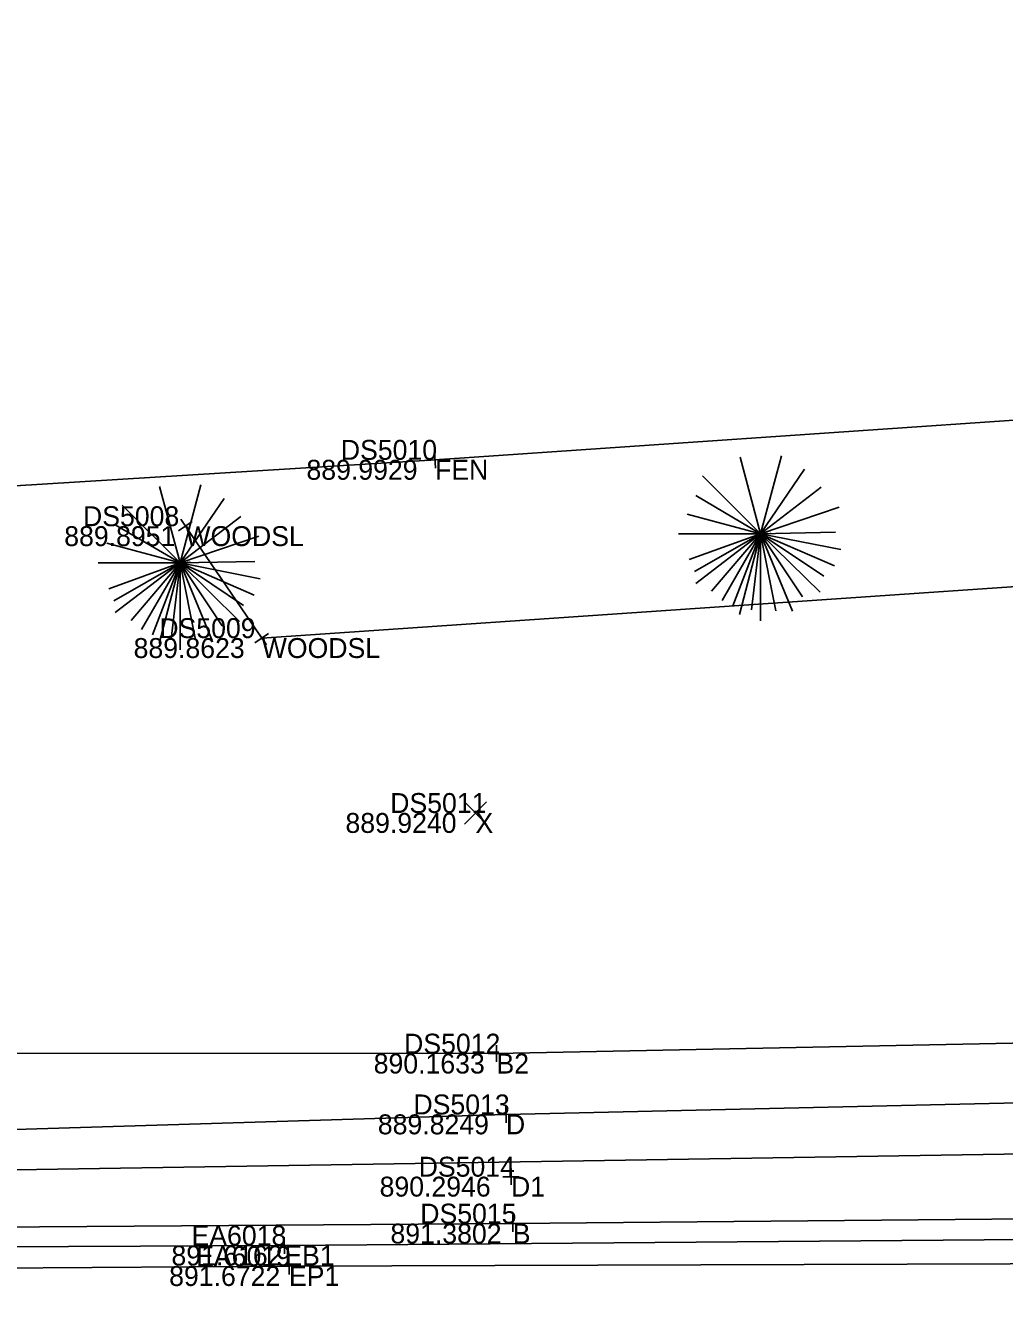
# Model space of a CAD drawing. Extents: x 179044 to 189691, y 286531 to 301257.
# Drawn here: x 179643.4 to 179702.4, y 300591.8 to 300668.9 of the extents above; entities that cross this region are included whole.
import ezdxf

# ---------------------------------------------------------------- set-up
doc = ezdxf.new("R2010")
doc.units = 0
for name, color, linetype in [('DR_X_Ditch', 7, 'Continuous'), ('PV_X_EOP', 7, 'Continuous'), ('PV_X_Shoulder_Aggregate', 7, 'Continuous'), ('RD_X_Fence', 7, 'Continuous'), ('SV_X_Break_Lines', 7, 'Continuous'), ('SV_X_Random_Point', 7, 'Continuous'), ('SV_X_Shot_Marker', 7, 'Continuous'), ('SV_X_Text_Comment', 7, 'Continuous'), ('SV_X_Text_Elevation', 7, 'Continuous'), ('SV_X_Text_Name', 7, 'Continuous'), ('VG_X_Cells', 7, 'Continuous'), ('VG_X_Text', 7, 'Continuous'), ('VG_X_Tree_Line_Rt', 7, 'Continuous')]:
    doc.layers.add(name, color=color, linetype=linetype)

msp = doc.modelspace()

# ---------------------------------------------------------------- linework, layer by layer
at = {"layer": 'DR_X_Ditch'}
msp.add_lwpolyline([(179564.56, 300599.962), (179672.339, 300603.26), (179771.172, 300605.494), (179880.337, 300606.441), (179984.937, 300607.328), (180077.947, 300608.965), (180127.19, 300616.843), (180132.045, 300619.573), (180144.286, 300623.545), (180155.547, 300629.29), (180160.465, 300633.547)], dxfattribs=at)
at = {"layer": 'PV_X_EOP'}
msp.add_lwpolyline([(179370.831, 300591.751), (179475.585, 300592.875), (179659.265, 300594.122), (179770.991, 300594.472), (179880.742, 300594.985), (179984.71, 300595.495), (180079.288, 300595.313), (180129.921, 300597.382), (180139.474, 300598.239), (180154.233, 300602.666), (180170.463, 300611.587), (180179.633, 300620.691), (180184.59, 300626.615), (180188.342, 300633.535), (180190.62, 300639.725), (180171.316, 300693.382), (180137.201, 300785.062), (180098.417, 300888.791)], dxfattribs=at)
at = {"layer": 'PV_X_Shoulder_Aggregate'}
msp.add_lwpolyline([(179563.565, 300594.924), (179658.987, 300595.359), (179770.596, 300596.259), (179881.565, 300597.129), (179984.257, 300597.357), (180079.139, 300597.322), (180129.307, 300600.299), (180139.964, 300601.425), (180153.02, 300605.118), (180169.97, 300613.883), (180177.635, 300623.691), (180181.654, 300635.111), (180182.998, 300649.235), (180167.771, 300692.69), (180134.639, 300784.201), (180095.484, 300888.508)], dxfattribs=at)
at = {"layer": 'RD_X_Fence'}
msp.add_lwpolyline([(180033.616, 300896.161), (180069.423, 300800.637), (180103.118, 300709.458), (180117.129, 300674.9), (180112.616, 300673.011), (180037.359, 300667.77), (179974.547, 300663.799), (179875.902, 300656.609), (179766.558, 300649.439), (179668.068, 300642.7), (179565.54, 300636.358)], dxfattribs=at)
at = {"layer": 'SV_X_Break_Lines'}
for points in [[(179564.638, 300606.986), (179671.768, 300606.922), (179771.087, 300608.912), (179880.599, 300615.611), (179986.884, 300616.02), (180078.033, 300615.521), (180124.742, 300624.492), (180128.289, 300624.221), (180137.303, 300629.118), (180148.459, 300633.708), (180154.503, 300636.496), (180146.307, 300651.241), (180135.969, 300673.811), (180118.542, 300716.074), (180095.911, 300772.35), (180076.611, 300824.96), (180047.5, 300900.199)], [(179564.191, 300598.682), (179770.809, 300601.942), (179880.33, 300600.557), (179984.707, 300602.17), (180076.298, 300602.513), (180129.447, 300605.473), (180133.823, 300610.665), (180143.543, 300612.063), (180154.911, 300619.358), (180168.807, 300625.749), (180172.898, 300631.66), (180174.527, 300641.071), (180168.307, 300660.619), (180157.537, 300688.57), (180123.865, 300779.294), (180087.271, 300883.216)], [(179564.385, 300595.92), (179672.75, 300596.68), (179770.459, 300597.562), (179880.51, 300598.544), (179984.703, 300599.007), (180076.342, 300598.773), (180129.476, 300602.027), (180135.94, 300603.814), (180151.807, 300606.879), (180162.976, 300612.722)]]:
    msp.add_lwpolyline(points, dxfattribs=at)
at = {"layer": 'SV_X_Random_Point'}
for p, q in [((179669.835, 300620.753), (179671.168, 300622.088)), ((179669.835, 300622.088), (179671.168, 300620.753))]:
    msp.add_line(p, q, dxfattribs=at)
at = {"layer": 'SV_X_Shot_Marker'}
for p, q in [((179668.567, 300642.735), (179667.569, 300642.666)), ((179668.102, 300642.202), (179668.034, 300643.199)), ((179668.068, 300642.7), (179668.068, 300642.7)), ((179653.439, 300638.984), (179652.613, 300638.42)), ((179652.744, 300639.115), (179653.308, 300638.289)), ((179653.026, 300638.702), (179653.026, 300638.702)), ((179658.037, 300632.241), (179657.211, 300631.677)), ((179657.343, 300632.372), (179657.906, 300631.546)), ((179657.624, 300631.959), (179657.624, 300631.959)), ((179671.768, 300607.422), (179671.768, 300606.422)), ((179671.268, 300606.922), (179672.268, 300606.921)), ((179671.768, 300606.922), (179671.768, 300606.922)), ((179671.839, 300603.245), (179672.839, 300603.276)), ((179672.324, 300603.76), (179672.354, 300602.761)), ((179672.339, 300603.26), (179672.339, 300603.26)), ((179672.144, 300599.508), (179673.144, 300599.508)), ((179672.644, 300600.008), (179672.644, 300599.008)), ((179672.644, 300599.508), (179672.644, 300599.508)), ((179672.746, 300597.18), (179672.753, 300596.18)), ((179672.25, 300596.676), (179673.25, 300596.683)), ((179672.75, 300596.68), (179672.75, 300596.68)), ((179658.985, 300595.859), (179658.989, 300594.859)), ((179658.487, 300595.357), (179659.487, 300595.361)), ((179658.987, 300595.359), (179658.987, 300595.359)), ((179658.765, 300594.119), (179659.765, 300594.126)), ((179659.262, 300594.622), (179659.268, 300593.623)), ((179659.265, 300594.122), (179659.265, 300594.122))]:
    msp.add_line(p, q, dxfattribs=at)
at = {"layer": 'VG_X_Cells'}
for p, q in [((179687.677, 300638.247), (179686.442, 300642.86)), ((179687.677, 300638.247), (179688.934, 300642.945)), ((179687.677, 300638.247), (179690.332, 300642.132)), ((179652.705, 300636.487), (179651.47, 300641.1)), ((179652.705, 300636.487), (179653.962, 300641.185)), ((179687.677, 300638.247), (179684.187, 300641.733)), ((179687.677, 300638.247), (179691.334, 300641.052)), ((179652.705, 300636.487), (179655.36, 300640.372)), ((179687.677, 300638.247), (179683.771, 300640.543)), ((179652.705, 300636.487), (179649.215, 300639.973)), ((179687.677, 300638.247), (179692.414, 300639.853)), ((179652.705, 300636.487), (179648.799, 300638.783)), ((179652.705, 300636.487), (179656.362, 300639.292)), ((179687.677, 300638.247), (179683.264, 300639.43)), ((179652.705, 300636.487), (179657.442, 300638.093)), ((179682.742, 300638.247), (179687.677, 300638.247)), ((179687.677, 300638.247), (179683.387, 300636.685)), ((179687.677, 300638.247), (179683.694, 300635.965)), ((179687.677, 300638.247), (179683.771, 300635.252)), ((179687.677, 300638.247), (179684.732, 300634.78)), ((179687.677, 300638.247), (179685.359, 300634.231)), ((179687.677, 300638.247), (179686.012, 300633.906)), ((179687.677, 300638.247), (179686.414, 300633.39)), ((179687.677, 300638.247), (179687.136, 300633.655)), ((179687.677, 300638.247), (179692.187, 300638.338)), ((179687.677, 300633.007), (179687.677, 300638.247)), ((179687.677, 300638.247), (179688.599, 300633.61)), ((179687.677, 300638.247), (179689.611, 300633.578)), ((179687.677, 300638.247), (179690.214, 300634.453)), ((179687.677, 300638.247), (179691.266, 300634.725)), ((179687.677, 300638.247), (179691.499, 300635.692)), ((179687.677, 300638.247), (179692.142, 300636.305)), ((179687.677, 300638.247), (179692.506, 300637.288)), ((179652.705, 300636.487), (179648.292, 300637.67)), ((179647.77, 300636.487), (179652.705, 300636.487)), ((179652.705, 300636.487), (179648.415, 300634.925)), ((179652.705, 300636.487), (179648.722, 300634.205)), ((179652.705, 300636.487), (179648.799, 300633.492)), ((179652.705, 300636.487), (179649.76, 300633.02)), ((179652.705, 300636.487), (179650.387, 300632.472)), ((179652.705, 300636.487), (179651.04, 300632.147)), ((179652.705, 300636.487), (179651.442, 300631.63)), ((179652.705, 300636.487), (179652.164, 300631.895)), ((179652.705, 300636.487), (179657.215, 300636.578)), ((179652.705, 300631.247), (179652.705, 300636.487)), ((179652.705, 300636.487), (179653.627, 300631.85)), ((179652.705, 300636.487), (179654.639, 300631.818)), ((179652.705, 300636.487), (179655.242, 300632.693)), ((179652.705, 300636.487), (179656.294, 300632.965)), ((179652.705, 300636.487), (179656.527, 300633.932)), ((179652.705, 300636.487), (179657.17, 300634.545)), ((179652.705, 300636.487), (179657.534, 300635.528))]:
    msp.add_line(p, q, dxfattribs=at)
at = {"layer": 'VG_X_Tree_Line_Rt'}
msp.add_lwpolyline([(179653.026, 300638.702), (179657.624, 300631.959), (179767.935, 300639.504), (179876.981, 300645.549), (179982.655, 300652.223), (180074.045, 300659.112), (180113.167, 300662.01), (180119.55, 300662.124), (180124.383, 300666.201), (180126.147, 300679.098), (180114.54, 300714.374), (180093.362, 300771.604), (180073.514, 300824.308), (180043.465, 300899.612)], dxfattribs=at)

# ---------------------------------------------------------------- texts
at = {"layer": 'SV_X_Text_Comment'}
for s, height, p in [('FEN', 1.2, (179668.068, 300641.5)), ('WOODSL', 1.2, (179653.026, 300637.502)), ('TE', 0.12, (179687.677, 300638.127)), ('TE', 0.12, (179652.705, 300636.367)), ('WOODSL', 1.2, (179657.624, 300630.759)), ('X', 1.2, (179670.501, 300620.221)), ('B2', 1.2, (179671.768, 300605.722)), ('D', 1.2, (179672.339, 300602.06)), ('D1', 1.2, (179672.644, 300598.308)), ('B', 1.2, (179672.75, 300595.48)), ('EB1', 1.2, (179658.987, 300594.159)), ('EP1', 1.2, (179659.265, 300592.922))]:
    msp.add_text(s, height=height, dxfattribs=at).set_placement(p)
at = {"layer": 'SV_X_Text_Elevation'}
for s, height, p in [('889.9929', 1.2, (179660.32, 300641.5)), ('889.8951', 1.2, (179645.726, 300637.502)), ('889.9080', 0.06, (179687.28, 300638.187)), ('889.8750', 0.06, (179652.315, 300636.427)), ('889.8623', 1.2, (179649.905, 300630.759)), ('889.9240', 1.2, (179662.669, 300620.221)), ('890.1633', 1.2, (179664.37, 300605.722)), ('889.8249', 1.2, (179664.62, 300602.06)), ('890.2946', 1.2, (179664.726, 300598.308)), ('891.3802', 1.2, (179665.381, 300595.48)), ('891.6162', 1.2, (179652.185, 300594.159)), ('891.6722', 1.2, (179652.047, 300592.922))]:
    msp.add_text(s, height=height, dxfattribs=at).set_placement(p)
at = {"layer": 'SV_X_Text_Name'}
for s, height, p in [('DS5010', 1.2, (179662.39, 300642.7)), ('DS5008', 1.2, (179646.856, 300638.702)), ('SV5013', 0.06, (179687.398, 300638.247)), ('SV5014', 0.06, (179652.426, 300636.487)), ('DS5009', 1.2, (179651.455, 300631.959)), ('DS5011', 1.2, (179665.365, 300621.421)), ('DS5012', 1.2, (179666.203, 300606.922)), ('DS5013', 1.2, (179666.765, 300603.26)), ('DS5014', 1.2, (179667.08, 300599.508)), ('DS5015', 1.2, (179667.176, 300596.68)), ('EA6018', 1.2, (179653.394, 300595.359)), ('EA6019', 1.2, (179653.672, 300594.122))]:
    msp.add_text(s, height=height, dxfattribs=at).set_placement(p)
at = {"layer": 'VG_X_Text'}
for p in [(179687.677, 300638.247), (179652.705, 300636.487)]:
    msp.add_text(' NOTE:6', height=0.12, dxfattribs=at).set_placement(p)

doc.saveas('drawing.dxf')
